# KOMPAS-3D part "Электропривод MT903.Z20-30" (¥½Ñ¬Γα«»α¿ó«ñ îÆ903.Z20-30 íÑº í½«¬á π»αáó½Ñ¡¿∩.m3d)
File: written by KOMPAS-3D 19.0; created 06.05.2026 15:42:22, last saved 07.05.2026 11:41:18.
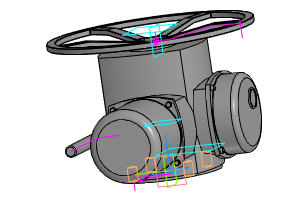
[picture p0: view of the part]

Document properties: Автор: Энергия; Полное имя файла: Z:\3.Личные\kachalov\3d для проектировщиков\2.2 Тип 47GVA, 47GVA.Z\Привод\Электропривод МТ903.Z20-30 без блока управления.m3d

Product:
- Part/product: Электропривод MT903.Z20-30
    Масса: 83.2154
  - Body: Тело 1
      Масса: 83.5296
  - Body: Тело 4
      Масса: 83.5296

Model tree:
1. Эскиз:1
2. Элемент выдавливания:1
     Расстояние 1 = 210
3. Эскиз:2
4. Элемент выдавливания:2
     Расстояние 1 = 150
5. Эскиз:3  (with: Элемент выдавливания:2)
6. Элемент выдавливания:3
     Расстояние 1 = 8
7. Эскиз:4  (with: Элемент выдавливания:3)
8. Элемент выдавливания:4
     Расстояние 1 = 120
9. Скругление:1  (with: Элемент выдавливания:4)
     Радиус = 15
10. Эскиз:5
11. Элемент выдавливания:5
     Расстояние 1 = 104
12. Эскиз:6  (with: Элемент выдавливания:5)
13. Элемент выдавливания:6
     Расстояние 1 = 8
14. Эскиз:7  (with: Элемент выдавливания:6)
15. Элемент выдавливания:7
     Расстояние 1 = 42
16. Скругление:2  (with: Элемент выдавливания:7)
     Радиус = 10
17. Эскиз:8
18. Элемент выдавливания:8
     Расстояние 1 = 157
19. Скругление:3  (with: Элемент выдавливания:8)
     Радиус = 5
20. Касательная плоскость:1  (with: Элемент выдавливания:8)
21. Эскиз:10
22. Элемент выдавливания:9
     Расстояние 1 = 5
23. Эскиз:11  (with: Элемент выдавливания:9)
24. Отверстие:1  (with: Элемент выдавливания:9)  (labels: M16)
     Глубина выреза = 26; Диаметр отверстия = 13.8349; Угол конуса дна = 118; Расстояние 1 = -49.4975; Расстояние 2 = -49.4975
25. M16  (with: Элемент выдавливания:9)  (labels: M16; cil0_24705-2004 coarse)
     Длина резьбы = 24; Шаг резьбы = 2; Номинальный диаметр резьбы = 16
26. Массив по концентрической сетке:1  (with: Отверстие:1, Эскиз:11)  (labels: M16)  (2 pattern instances)
27. M10  (with: Отверстие:1, Элемент выдавливания:9, Эскиз:11)  (labels: M16; cil0_24705-2004 coarse)  (1 pattern instances)
     Длина резьбы = 24; Шаг резьбы = 2; Номинальный диаметр резьбы = 16
28. Отверстие:1  (with: Эскиз:11)  (labels: M16)
29. Эскиз:12  (with: Элемент выдавливания:9)
30. Элемент выдавливания:10
     Расстояние 1 = 3
31. Эскиз:13  (with: Элемент выдавливания:10)
32. Элемент выдавливания:11
     Расстояние 2 = 50
33. Эскиз:14
34. Элемент выдавливания:14  (with: Элемент выдавливания:8)
     Расстояние 1 = 15; Расстояние 2 = 10
35. Эскиз:15  (with: Элемент выдавливания:1)
36. Элемент выдавливания:15
     Расстояние 1 = 5
37. Эскиз:16  (with: Элемент выдавливания:15)
38. Смещенная плоскость:1  (with: Элемент выдавливания:15)
     Расстояние = 25
39. Эскиз:17  (with: Элемент выдавливания:15)
40. Элемент выдавливания:16
     Расстояние 1 = 10
41. Элемент выдавливания:17
     Расстояние 1 = 10
42. Эскиз:20  (with: Элемент выдавливания:16, Элемент выдавливания:17)
43. Перпендикулярная плоскость:1
44. Эскиз:21
45. Элемент по траектории:1
46. Скругление:4  (with: Элемент выдавливания:17, Элемент по траектории:1, Элемент выдавливания:16)
     Радиус = 1
47. Массив по концентрической сетке:2  (with: Элемент по траектории:1, Эскиз:21, Скругление:4, Элемент выдавливания:15)  (5 pattern instances)
     Шаг 2 = 360
48. Скругление:5  (with: Элемент выдавливания:14, Элемент выдавливания:7, Элемент выдавливания:4)
     Радиус = 1
49. Эскиз:22  (with: Элемент выдавливания:3, Скругление:5)
50. Элемент выдавливания:18
     Расстояние 1 = 5
51. Скругление:6  (with: Элемент выдавливания:18)
     Радиус = 1
52. Массив по концентрической сетке:3  (with: Элемент выдавливания:18, Эскиз:22, Скругление:6, Элемент выдавливания:4)  (4 pattern instances)
     Шаг 2 = 360
53. Эскиз:23  (with: Элемент выдавливания:6, Скругление:5)
54. Элемент выдавливания:19
     Расстояние 1 = 5
55. Скругление:7  (with: Элемент выдавливания:19)
     Радиус = 1
56. Массив по концентрической сетке:4  (with: Элемент выдавливания:19, Эскиз:23, Скругление:7, Элемент выдавливания:7)  (4 pattern instances)
     Шаг 2 = 360
57. Эскиз:24
58. Элемент выдавливания:20
     Расстояние 1 = 40
59. Смещенная плоскость:2
60. Эскиз:25  (with: Элемент выдавливания:20)
61. Эскиз:26  (with: Элемент выдавливания:20)
62. Элемент по траектории:2
63. Фаска:1  (with: Элемент по траектории:2)
     Угол = 45; Длина 1 = 2; Длина 2 = 2
64. Эскиз:27  (with: Элемент выдавливания:7)
65. Элемент выдавливания:21
     Расстояние 1 = 3
66. Эскиз:28  (with: Элемент выдавливания:21)
67. Элемент выдавливания:22
     Расстояние 2 = 1

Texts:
  Точка начала. Х
  Точка начала. Y
  Точка начала. Z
